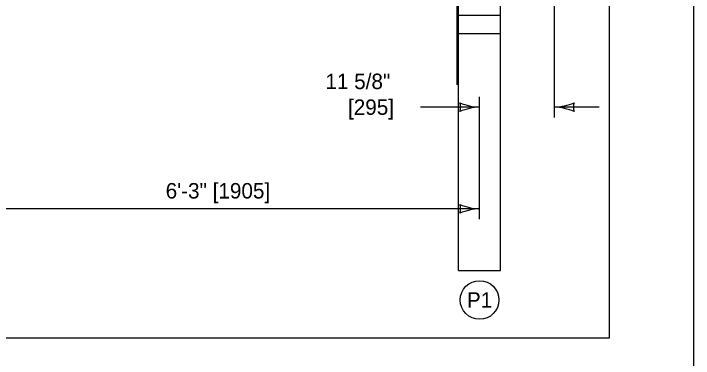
# Model space of a CAD drawing. Extents: x 49991.4 to 50021, y 49987.6 to 50011.4.
# Drawn here: x 50014.114 to 50016.75, y 49992.639 to 49993.977 of the extents above; entities that cross this region are included whole.
import ezdxf

# ---------------------------------------------------------------- set-up
doc = ezdxf.new("R2010")
doc.units = 0
for name, color, linetype in [('Level 1', 7, 'Continuous'), ('Level 2', 7, 'Continuous'), ('Level 3', 7, 'Continuous'), ('Level 4', 7, 'Continuous'), ('Level 6', 7, 'Continuous')]:
    doc.layers.add(name, color=color, linetype=linetype)

msp = doc.modelspace()

# ---------------------------------------------------------------- linework, layer by layer
at = {"layer": 'Level 1'}
msp.add_lwpolyline([(49999.3835, 49998.9992), (50016.7501, 49998.9992), (50016.7501, 49987.7988), (49999.3835, 49987.7988)], close=True, dxfattribs=at)
at = {"layer": 'Level 2'}
msp.add_circle((50015.9211, 49992.8655), 0.075, dxfattribs=at)
at = {"layer": 'Level 3'}
for p, q in [((50016.2117, 49993.574), (50016.2117, 49994.6384)), ((50015.9211, 49993.1794), (50015.9211, 49993.654)), ((50015.9211, 49993.614), (50015.6915, 49993.614)), ((50016.3851, 49993.614), (50016.2117, 49993.614)), ((50015.9211, 49993.2194), (50014.0221, 49993.2194))]:
    msp.add_line(p, q, dxfattribs=at)
for centre, radius, start, end in [((50015.9303, 49993.8361), 0.2223, 247.456, 267.6395), ((50015.7929, 49993.614), 0.0548, 342.1388, 17.8612), ((50016.2002, 49993.8467), 0.233, 272.8273, 292.0772), ((50016.3399, 49993.614), 0.0548, 162.1388, 197.8612), ((50015.9326, 49993.3813), 0.233, 92.8273, 112.0772), ((50016.2025, 49993.3918), 0.2223, 67.456, 87.6395), ((50015.9303, 49993.4415), 0.2223, 247.456, 267.6395), ((50015.7929, 49993.2194), 0.0548, 342.1388, 17.8612), ((50015.9326, 49992.9867), 0.233, 92.8273, 112.0772)]:
    msp.add_arc(centre, radius, start, end, dxfattribs=at)
at = {"layer": 'Level 4'}
for p, q in [((50015.8395, 49992.9805), (50015.8395, 49994.335)), ((50016.0027, 49992.9805), (50016.0027, 49994.335)), ((50015.8332, 49994.1661), (50015.8332, 49993.7022)), ((50016.0027, 49993.9696), (50015.8395, 49993.9696)), ((50016.0027, 49993.8987), (50015.8395, 49993.8987)), ((50015.8395, 49993.7022), (50015.8332, 49993.7022)), ((50015.8395, 49992.9805), (50016.0027, 49992.9805))]:
    msp.add_line(p, q, dxfattribs=at)
at = {"layer": 'Level 6'}
msp.add_line((50016.4251, 49992.7184), (50016.4251, 49995.6872), dxfattribs=at)
msp.add_lwpolyline([(50013.832, 49993.1194), (50013.832, 49992.7184), (50016.4251, 49992.7184)], dxfattribs=at)

# ---------------------------------------------------------------- texts
at = {"layer": 'Level 2'}
for s, p in [('11 5/8"', (50015.3234, 49993.684)), ('[295]', (50015.411, 49993.584)), ('6\'-3" [1905]', (50014.7041, 49993.2594)), ('P1', (50015.8719, 49992.8355))]:
    msp.add_text(s, height=0.06, dxfattribs=at).set_placement(p)

doc.saveas('drawing.dxf')
